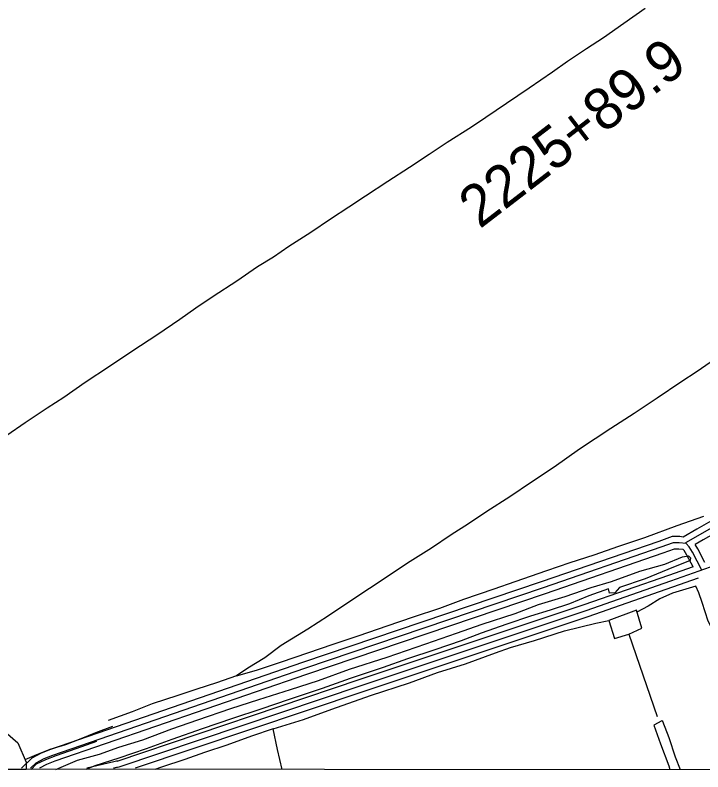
# Model space of a CAD drawing. Extents: x 3245246 to 3283090, y 806824 to 832173.
# Drawn here: x 3267152 to 3268806, y 812200 to 814018 of the extents above; entities that cross this region are included whole.
import ezdxf

# ---------------------------------------------------------------- set-up
doc = ezdxf.new("R2010")
doc.units = 0
for name, color, linetype in [('V-GRID-FRAM', 7, 'Continuous'), ('V-ROAD-CNTR', 7, 'Continuous'), ('V-SITE-VEGE', 7, 'Continuous'), ('V-SURV-IDEN', 7, 'Continuous'), ('V-TOPO-SHOR', 7, 'Continuous')]:
    doc.layers.add(name, color=color, linetype=linetype)

msp = doc.modelspace()

# ---------------------------------------------------------------- linework, layer by layer
at = {"layer": 'V-GRID-FRAM'}
msp.add_lwpolyline([(3249428.8, 830400), (3280833.3, 830386.3), (3280833.3, 812199.6), (3249412.9, 812213.3), (3249428.8, 830400)], dxfattribs=at)
at = {"layer": 'V-ROAD-CNTR'}
for points in [[(3269675.3, 812980.7), (3269482.6, 812918), (3269027.2, 812763.8), (3268727.9, 812657.6), (3268524, 812586.4), (3267985.6, 812407), (3267401, 812210.6)], [(3269401.6, 812993.5), (3268824.9, 812802.2), (3268791.4, 812783), (3268758.5, 812764)], [(3269406.3, 812979.2), (3268831, 812788.5), (3268798.9, 812770), (3268763.9, 812749.8)], [(3269411, 812965), (3268837.2, 812774.7), (3268806.3, 812757), (3268787, 812745.8)], [(3268758.5, 812764), (3268749.8, 812764.9), (3268731.6, 812765.2), (3268699.6, 812753.6), (3268417, 812656.1), (3267842.6, 812462.3), (3267237, 812253.3), (3267214.5, 812244.9), (3267192.5, 812232.7), (3267167.1, 812208.2)], [(3268803.2, 812684.3), (3268780.3, 812727.8), (3268772.6, 812740.7), (3268765.5, 812748.1), (3268748.9, 812749.9), (3268734.1, 812750.2), (3268704.6, 812739.5), (3268421.9, 812641.9), (3267847.5, 812448.1), (3267242.1, 812239.1), (3267220.8, 812231.2), (3267201.5, 812220.5), (3267189.2, 812208.6), (3267189.1, 812208.2)], [(3268810.4, 812702.8), (3268793.4, 812735.2), (3268787, 812745.8)], [(3268781.8, 812692.7), (3268767.3, 812720.4), (3268760.6, 812731.5), (3268758.4, 812733.8), (3268747.9, 812734.9), (3268736.6, 812735.1), (3268709.6, 812725.4), (3268426.7, 812627.8), (3267852.3, 812433.9), (3267247.2, 812225), (3267227.1, 812217.5), (3267210.2, 812208.2)], [(3268781.8, 812692.7), (3268722.9, 812671.8), (3268519.2, 812600.6), (3267980.8, 812421.2), (3267396.2, 812224.8)], [(3268794, 812665.2), (3268732.9, 812643.5), (3268528.9, 812572.2), (3267990.4, 812392.8), (3267440.5, 812208.1)], [(3267347.8, 812272.3), (3267298.2, 812255.3), (3267249.7, 812238.2), (3267225.3, 812228.3), (3267202.7, 812218.1), (3267190.9, 812205.5)], [(3267398.7, 812225.4), (3267395.7, 812225), (3267392.5, 812224.4), (3267389.3, 812223.7), (3267324.5, 812208.1)], [(3267401, 812210.6), (3267398.2, 812210.2), (3267395.4, 812209.7), (3267392.6, 812209.1), (3267389.8, 812208.4), (3267388.6, 812208.1)]]:
    msp.add_lwpolyline(points, dxfattribs=at)
at = {"layer": 'V-SITE-VEGE'}
for p, q in [((3267105, 812315.8), (3267158.2, 812269.2)), ((3267158.2, 812269.2), (3267178.2, 812222.7)), ((3267178.2, 812222.7), (3267178.2, 812205.5)), ((3267178.2, 812205.5), (3266854.9, 812205.7))]:
    msp.add_line(p, q, dxfattribs=at)
at = {"layer": 'V-TOPO-SHOR'}
msp.add_line((3268627.5, 812530.5), (3268696, 812332.4), dxfattribs=at)
for points in [[(3268666.8, 814034.1), (3268615.1, 813998.3), (3268566.4, 813963.5), (3268526, 813937.6), (3268480.4, 813906.6), (3268444.3, 813881.3), (3268387.8, 813842.5), (3268333.6, 813806.1)], [(3268333.6, 813806.1), (3268283.4, 813772.5), (3268249, 813749), (3268190.4, 813712), (3268147.4, 813683.2), (3268100.4, 813652.4), (3268047.7, 813618), (3267994.3, 813583), (3267954.7, 813556.8), (3267910.3, 813527.7), (3267862.6, 813496.1), (3267809.9, 813462.1), (3267773.2, 813436.9), (3267735, 813413.3), (3267685, 813379.2), (3267628.3, 813342.2), (3267586.6, 813313.6), (3267548.1, 813287.1), (3267492.5, 813248.9)], [(3269082.2, 813355.7), (3269028.5, 813320.7), (3268979.7, 813286.7), (3268965.3, 813275.5), (3268922.2, 813248.9), (3268874.4, 813217.2), (3268833.4, 813190.8), (3268792.1, 813161.4), (3268752.7, 813136.3), (3268695.5, 813097.9), (3268640.7, 813061.2), (3268584, 813024.4), (3268509.3, 812974.8), (3268448.2, 812931.8)], [(3267492.5, 813248.9), (3267434.7, 813211.6), (3267379, 813174), (3267320.3, 813135.3), (3267269.4, 813099.3), (3267229, 813073.4), (3267176.3, 813038.1), (3267131.9, 813007.6), (3267080.8, 812974.8), (3267032.7, 812942.4), (3266989.7, 812913.5), (3266940.8, 812881.2), (3266920, 812867.2), (3266860.3, 812827.1), (3266806.2, 812791.8), (3266762.3, 812762.7), (3266709.2, 812725.4), (3266667.8, 812696.8), (3266633.7, 812673.1), (3266603.9, 812651.2)], [(3268448.2, 812931.8), (3268393.6, 812895.7), (3268341.3, 812860.3), (3268286.1, 812825.2), (3268242, 812795.6), (3268200.7, 812769.2), (3268152.7, 812737), (3268095.5, 812701.1), (3268051.6, 812671.8), (3268003.6, 812640.2), (3267952.2, 812606.2), (3267905.5, 812574.4), (3267856.1, 812542.4), (3267791.9, 812503), (3267752.7, 812473.8), (3267711.2, 812448.9), (3267684.1, 812430.1)], [(3267684.1, 812430.1), (3267732.6, 812443.8), (3267792.4, 812464.4), (3267855.9, 812485.5), (3267916.5, 812506.5), (3267979.4, 812527.5), (3268046.6, 812550.3), (3268109.7, 812571.8), (3268173.3, 812593.3), (3268230.5, 812614.3), (3268303.6, 812639.4), (3268354.4, 812656.8), (3268430.3, 812683.7), (3268486.6, 812702.4), (3268543.9, 812721.1), (3268603.7, 812741.8), (3268666.3, 812762.9), (3268744, 812791.4), (3268808.2, 812813.7)], [(3267249.6, 812205.5), (3267257.2, 812208.5), (3267302, 812227.4), (3267355.1, 812242.2), (3267401.7, 812258.8), (3267459.1, 812276.2), (3267528.4, 812302.6), (3267591.1, 812324.4), (3267670.3, 812351.9), (3267737.6, 812373.7), (3267814.3, 812397.4), (3267881.3, 812419), (3267956.2, 812446.2), (3268046.2, 812475.6), (3268139.4, 812507.1), (3268213.2, 812532.6), (3268275.1, 812554.7), (3268354.6, 812580.1), (3268410.4, 812601.7), (3268474.2, 812621.4), (3268537.1, 812642.5), (3268586.1, 812657.1), (3268654.2, 812681.7), (3268713.7, 812698.7), (3268756.8, 812716.2), (3268771.1, 812718.7), (3268775.9, 812714.2), (3268775.3, 812707.2), (3268721.3, 812685.9), (3268666.5, 812663.2), (3268604.8, 812642.8), (3268594.2, 812630.2), (3268581, 812629.3), (3268578.5, 812639.2), (3268531.2, 812622.9)], [(3268889.5, 812427.1), (3268865.1, 812471.2), (3268840.4, 812517.8), (3268818.6, 812561.5), (3268804.2, 812606.8), (3268795.7, 812629.6), (3268789, 812645.9), (3268732.9, 812628.9), (3268702.4, 812615.2), (3268673.7, 812597.7), (3268647.1, 812583.1)], [(3268531.2, 812622.9), (3268484.8, 812603.5), (3268438.7, 812587.9), (3268391, 812574), (3268334, 812554.4), (3268272.4, 812532.7), (3268224.1, 812514.6), (3268160.8, 812492.6), (3268095.2, 812471.3), (3268036.7, 812450.6), (3267957.7, 812423.8), (3267889.8, 812400.3), (3267810.8, 812373.3), (3267742.7, 812350.4), (3267674.8, 812328), (3267601.5, 812303.2), (3267528.4, 812277.6), (3267466.8, 812255.3), (3267401, 812232.5), (3267343.4, 812214), (3267321.8, 812205.5)], [(3268579.4, 812563.7), (3268593.2, 812519.9), (3268627.5, 812530.5), (3268658.6, 812544.9), (3268645.6, 812588.1), (3268579.4, 812563.7)], [(3267845.3, 812325.5), (3267913.2, 812350.5), (3268006.6, 812383), (3268100.4, 812413.9), (3268167.7, 812438.6), (3268235, 812459.4), (3268307.1, 812485.7), (3268343.3, 812498.3), (3268400.8, 812514.9), (3268473, 812538.3), (3268548.3, 812556.7), (3268579.4, 812563.7)], [(3267684.1, 812430.1), (3267636.4, 812413.6), (3267588.5, 812398), (3267542.8, 812383.2), (3267481.8, 812363), (3267433.7, 812344.1), (3267375.7, 812323.3)], [(3267793.9, 812205.3), (3267782.7, 812253.5), (3267772.1, 812302.9), (3267845.3, 812325.5)], [(3267386.3, 812308.5), (3267345, 812293.1), (3267305.8, 812277.3), (3267272.8, 812264.6), (3267235.4, 812253.1), (3267203.7, 812240.4), (3267175.1, 812228.2)], [(3268751.6, 812204.8), (3268740, 812234.8), (3268724.6, 812281.3), (3268709.3, 812320.3), (3268706.7, 812322.6), (3268687.7, 812312), (3268703.6, 812266.9), (3268723.4, 812213.7), (3268726.4, 812204.9)], [(3267772.1, 812302.9), (3267720.5, 812285.6), (3267660.7, 812263.9), (3267607.1, 812246.4), (3267560.3, 812229), (3267503.6, 812210.6), (3267487.6, 812205.4)]]:
    msp.add_lwpolyline(points, dxfattribs=at)

# ---------------------------------------------------------------- texts
at = {"layer": 'V-SURV-IDEN'}
msp.add_text('2225+89.9', height=100, rotation=37.5556, dxfattribs=at).set_placement((3268269.1, 813503.1))

doc.saveas('drawing.dxf')
